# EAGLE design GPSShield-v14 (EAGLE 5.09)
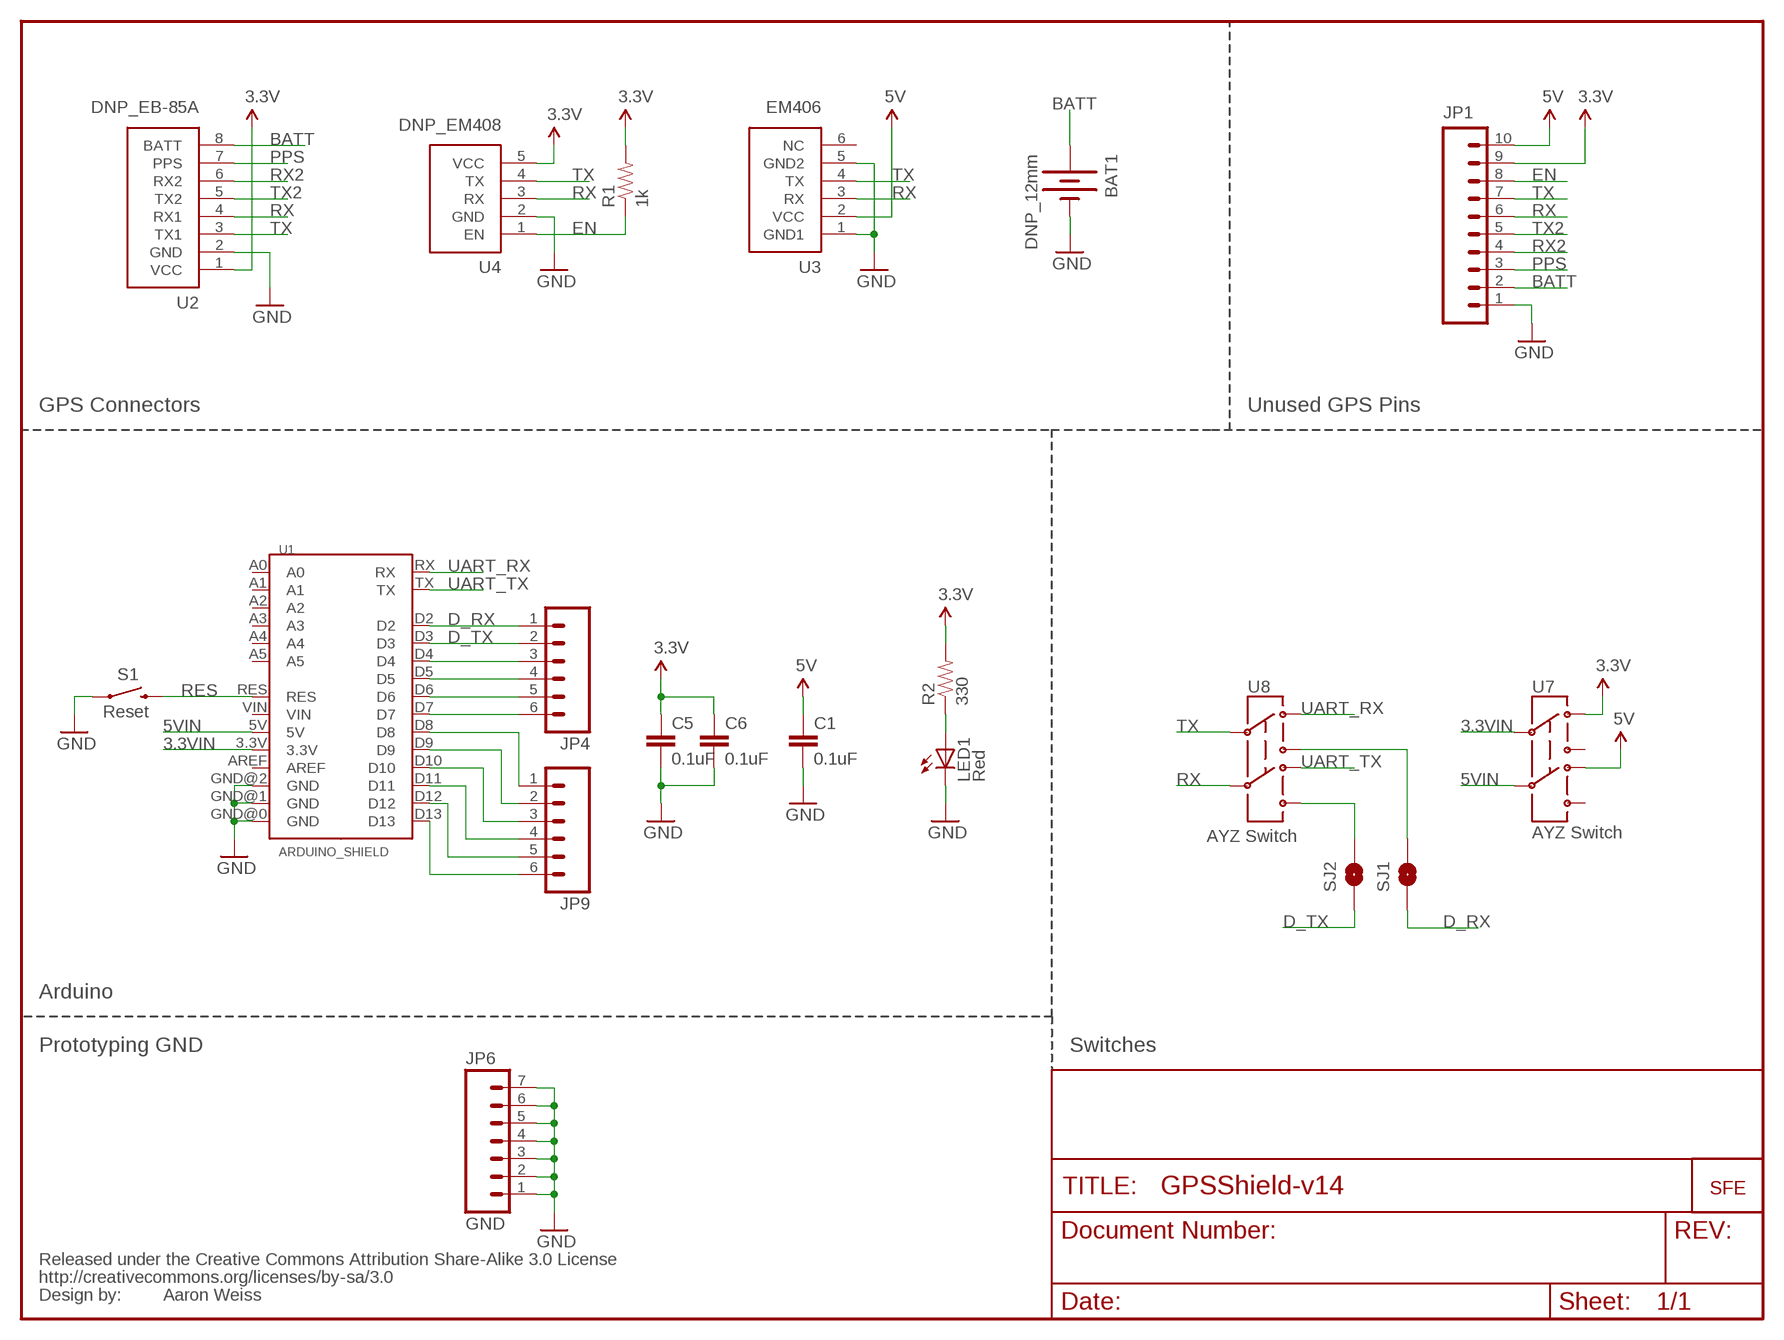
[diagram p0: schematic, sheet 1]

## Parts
BAT1  DNP_12mm  BATTERY12MM  [BATTCON_12MM]
C1  0.1uF  CAP0402-CAP  [0402-CAP]
C5  0.1uF  CAP0402-CAP  [0402-CAP]
C6  0.1uF  CAP0402-CAP  [0402-CAP]
JP1  M10"  [1X10]
JP3  LOGO-SFENEW  [SFE-NEW-WEBLOGO]
JP4  M06SIP  [1X06]
JP6  GND  M07  [1X07]
JP9  M06SIP  [1X06]
LED1  Red  LED0603  [LED-0603]
R1  1k  RESISTOR0402-RES  [0402-RES]
R2  330  RESISTOR0402-RES  [0402-RES]
S1  Reset  SWITCH-MOMENTARY-2SMD  [TACTILE_SWITCH_SMD]
SJ1  D_RX  SOLDERJUMPERNC  [SJ_2S]
SJ2  D_TX  SOLDERJUMPERNC  [SJ_2S]
U1  ARDUINO_SHIELD  [DUEMILANOVE_SHIELD]
U2  DNP_EB-85A  EB-85ASMD  [EB-85A]
U3  EM406  [EM406]
U4  DNP_EM408  EM408_CON  [EM408_CON]
U7  AYZ Switch  SWITCH-DPDTSMD  [AYZ0202]
U8  AYZ Switch  SWITCH-DPDTSMD  [AYZ0202]
U$1  CREATIVE_COMMONS  [CREATIVE_COMMONS]

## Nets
3.3V: C5.1 C6.1 JP1.9 R1.2 R2.2 U2.1(VCC) U4.5(VCC) U7.1
3.3VIN: U1.3.3V U7.2
5V: C1.1 JP1.10 U3.2(VCC) U7.4
5VIN: U1.5V U7.5
BATT: BAT1.PWR@1(+) JP1.2 U2.8(BATT)
D_RX: JP4.1 SJ1.1 U1.D2
D_TX: JP4.2 SJ2.1 U1.D3
EN: JP1.8 R1.1 U4.1(EN)
GND: BAT1.GND(-) C1.2 C5.2 C6.2 JP1.1 JP6.1 JP6.2 JP6.3 JP6.4 JP6.5 JP6.6 JP6.7 LED1.C S1.1 U1.GND@0(GND) U1.GND@1(GND) U1.GND@2(GND) U2.2(GND) U3.1(GND1) U3.5(GND2) U4.2(GND)
N$1: LED1.A R2.1
N$111: JP4.3 U1.D4
N$112: JP4.4 U1.D5
N$113: JP4.5 U1.D6
N$114: JP4.6 U1.D7
N$115: JP9.1 U1.D8
N$116: JP9.2 U1.D9
N$117: JP9.3 U1.D10
N$118: JP9.4 U1.D11
N$119: JP9.5 U1.D12
N$120: JP9.6 U1.D13
N$121: SJ2.2 U8.6
N$122: SJ1.2 U8.3
PPS: JP1.3 U2.7(PPS)
RES: S1.3 U1.RES
RX: JP1.6 U2.4(RX1) U3.3(RX) U4.3(RX) U8.5
RX2: JP1.4 U2.6(RX2)
TX: JP1.7 U2.3(TX1) U3.4(TX) U4.4(TX) U8.2
TX2: JP1.5 U2.5(TX2)
UART_RX: U1.RX U8.1
UART_TX: U1.TX U8.4
Unconnected: U1.A0 U1.A1 U1.A2 U1.A3 U1.A4 U1.A5 U1.AREF U1.VIN U3.6(NC) U7.3 U7.6

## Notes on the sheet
- GPS Connectors | Unused GPS Pins
- Arduino
- Prototyping GND | Switches
- Aaron Weiss

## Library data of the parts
BAT1 = SparkFun:BATTERY: Battery Holders
C1 C5 C6 = SparkFun:CAP: Capacitor
JP1 = SparkFun:M10: Header 10 Standard 10-pin 0.1" header. Use with straight break away headers (SKU : PRT-00116), right angle break away headers (PRT-00553), swiss pins (PRT-00743), machine pins (PRT-00117), and female headers (PRT-00115).
JP3 = SparkFun:LOGO-SFE: Spark Fun Electronics PCB Logo
JP4 JP9 = SparkFun:M06: Header 6 Standard 6-pin 0.1" header. Use with straight break away headers (SKU : PRT-00116), right angle break away headers (PRT-00553), swiss pins (PRT-00743), machine pins (PRT-00117), and female headers (PRT-00115). Molex polarized connector foot print use with SKU : PRT-08094 with associated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
JP6 = SparkFun:M07: Header 7 Standard 7-pin 0.1" header. Use with straight break away headers (SKU : PRT-00116), right angle break away headers (PRT-00553), swiss pins (PRT-00743), machine pins (PRT-00117), and female headers (PRT-00115). NOTES ON THE VARIANTS LOCK and LOCK_LONGPADS... This footprint was designed to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
LED1 = SparkFun:LED: LEDs
R1 R2 = SparkFun:RESISTOR: Resistor
S1 = SparkFun:SWITCH-MOMENTARY-2
SJ1 SJ2 = SparkFun:SOLDERJUMPER: Solder Jumper
U1 = SparkFun:ARDUINO_SHIELD
U2 = SparkFun:EB-85A: EB-85A Connector Proven layout and schematic for ETek 5Hz GPS receiver connector. Spark Fun Electronics SKU : GPS-08297
U3 = SparkFun:EM406: EM406 Connector Proven layout and schematic for EM406 connector. Spark Fun Electronics SKU : GPS-00579
U4 = SparkFun:EM408_CON: This is the mating connector for the EM408 GPS receiver. The EM408 connects to the board via a cable, this connector footprint does not include the outline of the receiver. You should include the "EM408_Outline" device in your schematic if you are to use the EM408 in your design.
U7 U8 = SparkFun:SWITCH-DPDT: DPDT Version of the COM-00597, MSS22 is a 125VAC @ 300mA rated switch
U$1 = SparkFun:CREATIVE_COMMONS

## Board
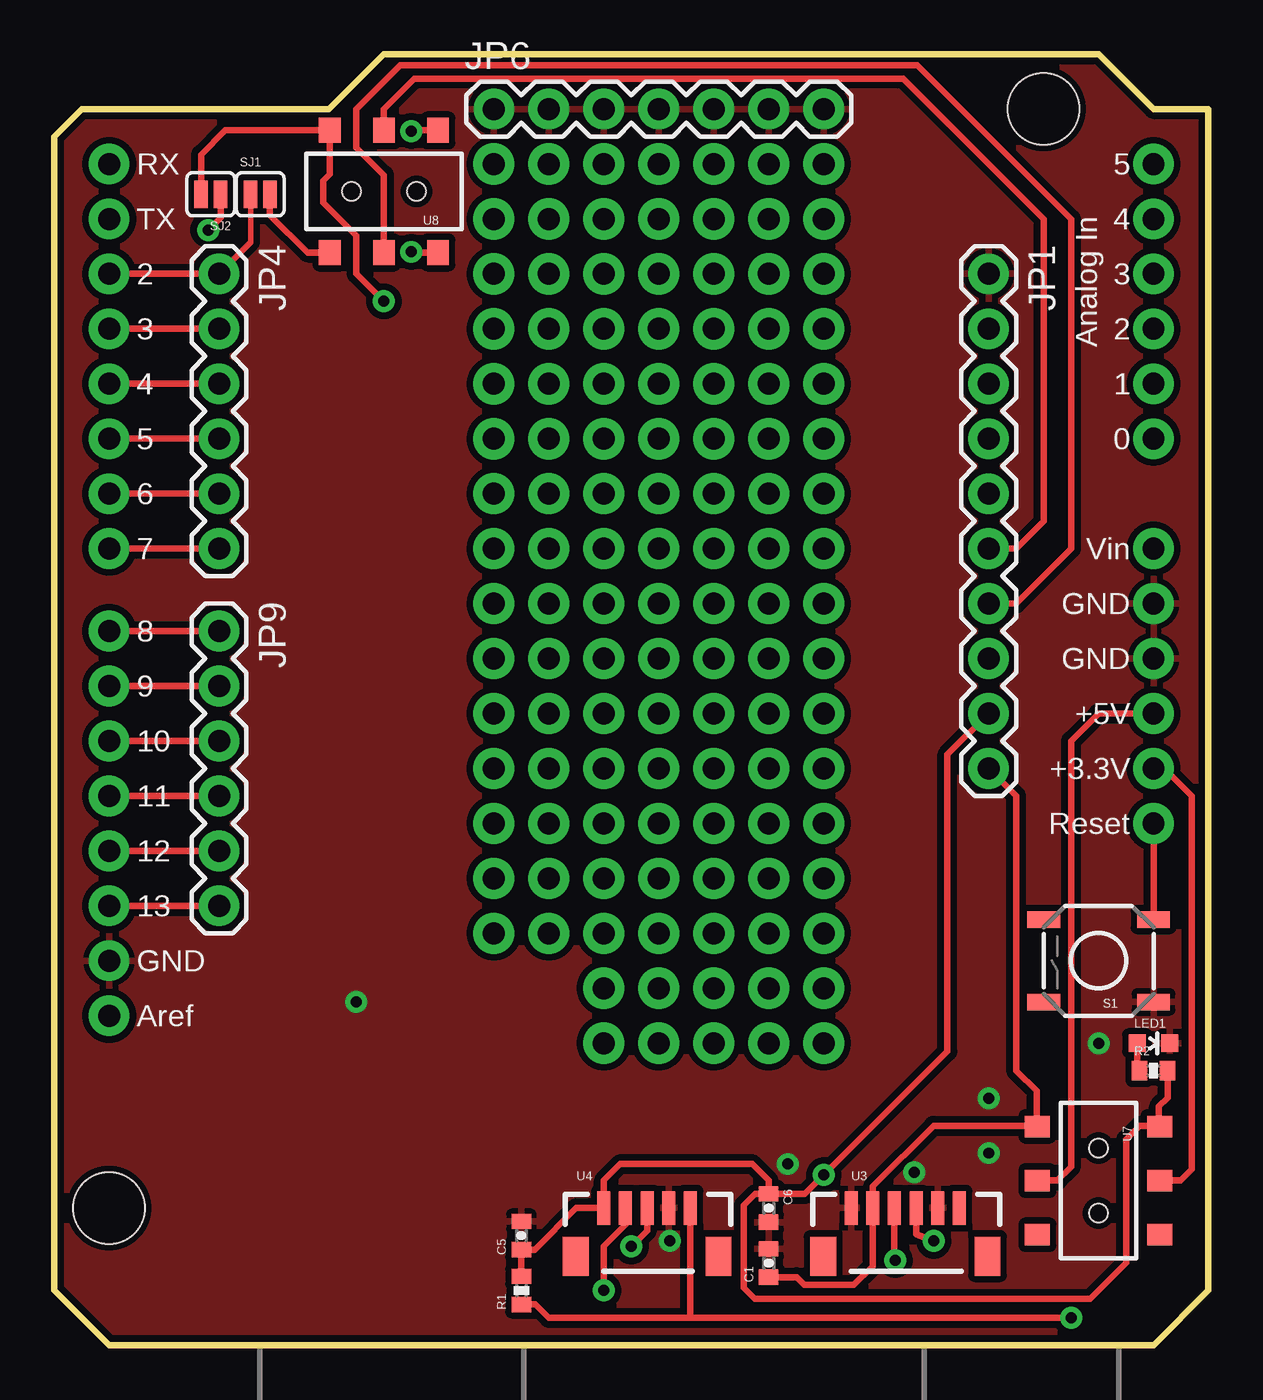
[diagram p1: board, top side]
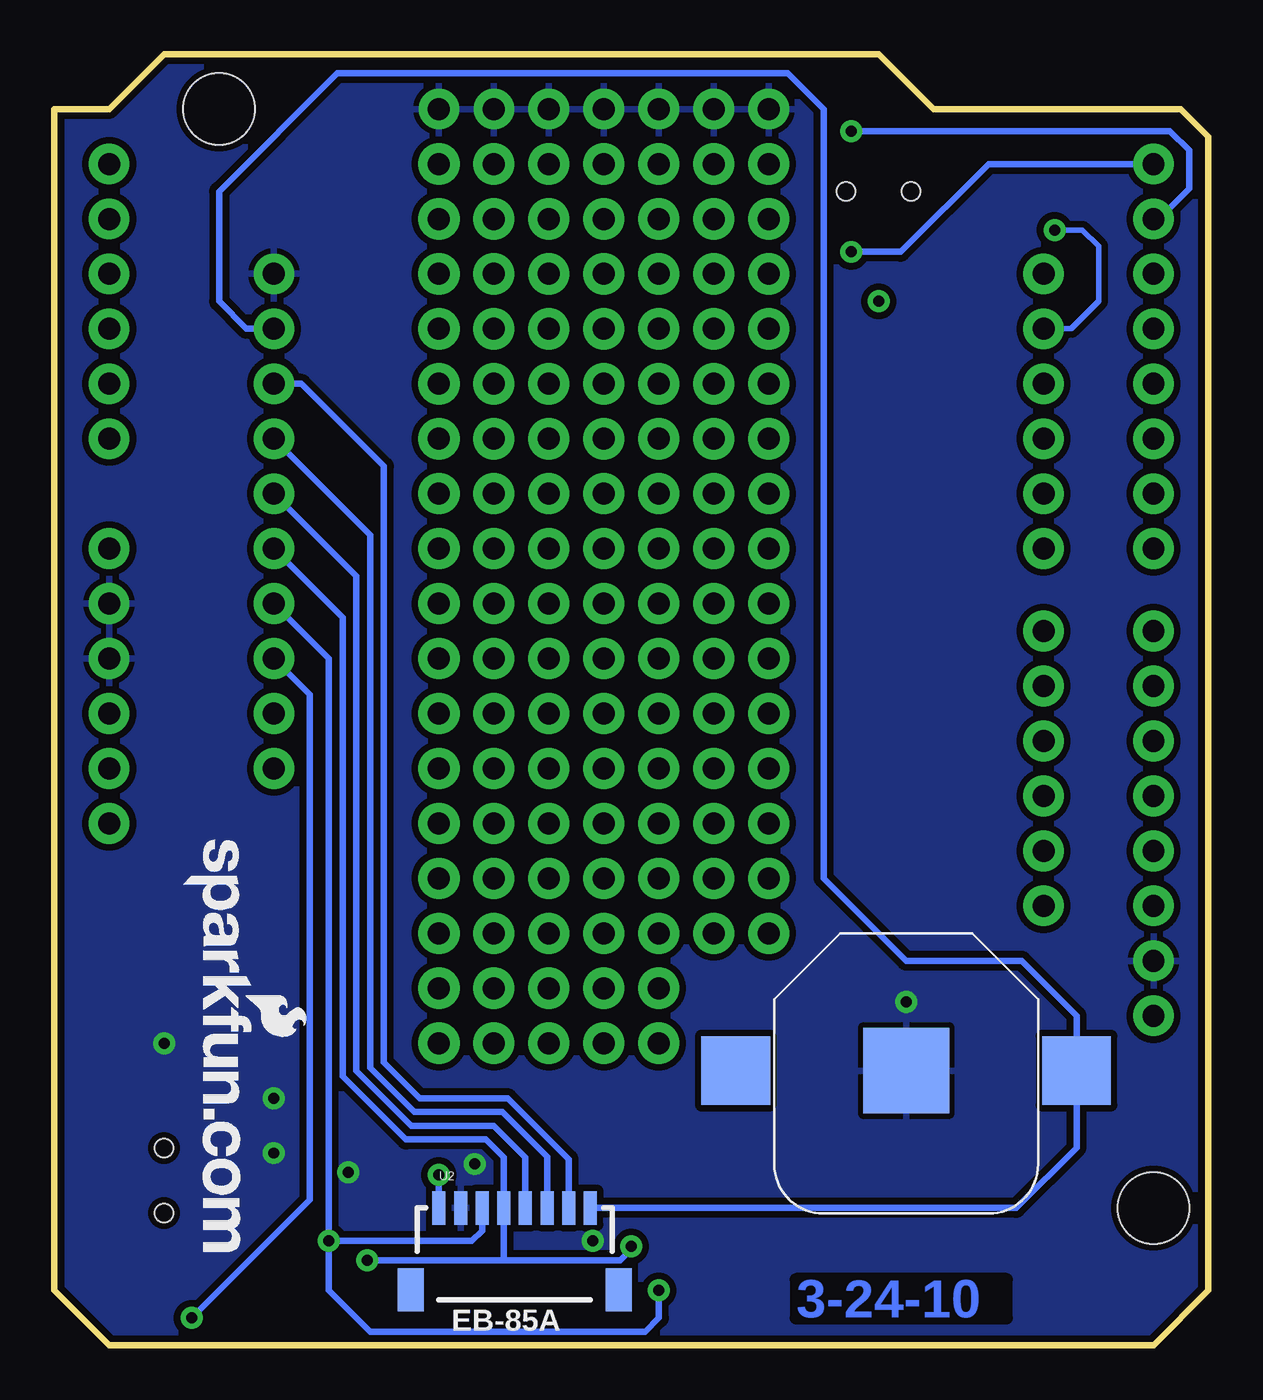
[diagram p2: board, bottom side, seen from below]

Size 53.34 x 59.69 mm. Coordinates in mm from the lower left corner, seen from the top.
Outline: 2.54,0 0,2.54 0,55.88 1.27,57.15 12.7,57.15 15.24,59.69 48.26,59.69 50.8,57.15 53.34,57.15 53.34,2.54 50.8,0 2.54,0
Copper layers (1*16): Top 0.035mm / dielectric 1.5mm / Bottom 0.035mm
Design rules "SparkFun": minimum track width 8mil, minimum drill 20mil, track to track 8mil, track to pad 8mil, pad to pad 8mil, via to via 8mil, smd to smd 8mil, copper to edge 8mil, drill to drill 8mil, minimum pad ring 12mil, minimum via ring 10mil, stop-mask expansion 4mil, vias tented up to drill 20mil, thermal gap 10mil

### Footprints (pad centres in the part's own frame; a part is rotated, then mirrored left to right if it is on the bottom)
BATTCON_12MM = smd 3.962 x 3.962: GND 0,0 | smd 3.175 x 3.175: PWR@1 -7.874,0; PWR@2 7.874,0
0402-CAP = smd 0.7 x 0.9: 1 -0.65,0; 2 0.65,0
1X10 = drill 1.016 pad 1.88 round: 1 0,0; 2 2.54,0; 3 5.08,0; 4 7.62,0; 5 10.16,0; 6 12.7,0; 7 15.24,0; 8 17.78,0; 9 20.32,0; 10 22.86,0
1X06 = drill 1.016 pad 1.88 round: 1 0,0; 2 2.54,0; 3 5.08,0; 4 7.62,0; 5 10.16,0; 6 12.7,0
1X07 = drill 1.016 pad 1.88 round: 1 0,0; 2 2.54,0; 3 5.08,0; 4 7.62,0; 5 10.16,0; 6 12.7,0; 7 15.24,0
LED-0603 = smd 0.8 x 0.8: A 0,-0.75; C 0,0.75
0402-RES = smd 0.7 x 0.9: 1 -0.65,0; 2 0.65,0
TACTILE_SWITCH_SMD = smd 1.524 x 0.762: 1 -2.54,1.905; 2 2.54,1.905; 3 -2.54,-1.905; 4 2.54,-1.905
SJ_2S = smd 0.635 x 1.27: 1 -0.45,0; 2 0.45,0
DUEMILANOVE_SHIELD = drill 1.016 pad 1.88 round: 3.3V 50.8,26.67; 5V 50.8,29.21; A0 50.8,41.91; A1 50.8,44.45; A2 50.8,46.99; A3 50.8,49.53; A4 50.8,52.07; A5 50.8,54.61; AREF 2.54,15.24; D2 2.54,49.53; D3 2.54,46.99; D4 2.54,44.45; D5 2.54,41.91; D6 2.54,39.37; D7 2.54,36.83; D8 2.54,33.02; D9 2.54,30.48; D10 2.54,27.94; D11 2.54,25.4; D12 2.54,22.86; D13 2.54,20.32; GND@0 50.8,31.75; GND@1 50.8,34.29; GND@2 2.54,17.78; RES 50.8,24.13; RX 2.54,54.61; TX 2.54,52.07; VIN 50.8,36.83 | hole 3.302: 45.72,57.15; 2.54,6.35
EB-85A = smd 0.6 x 1.55: 1 0,0; 2 1,0; 3 2,0; 4 3,0; 5 4,0; 6 5,0; 7 6,0; 8 7,0 | smd 1.2 x 2: P$1 -1.3,-3.775; P$2 8.3,-3.775
EM406 = smd 0.6 x 1.55: 1 0,0; 2 1,0; 3 2,0; 4 3,0; 5 4,0; 6 5,0 | smd 1.2 x 1.8: P$1 -1.3,-2.225; P$2 6.3,-2.225
EM408_CON = smd 0.6 x 1.55: 1 4,0; 2 3,0; 3 2,0; 4 1,0; 5 0,0 | smd 1.2 x 1.8: P$1 -1.3,-2.225; P$2 5.3,-2.225
AYZ0202 = smd 1 x 1.15: 1 -2.5,2.825; 2 0,2.825; 3 2.5,2.825; 4 -2.5,-2.825; 5 0,-2.825; 6 2.5,-2.825 | hole 0.85: 1.5,0; -1.5,0

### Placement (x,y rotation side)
BAT1  13.97,12.7 180 bottom
C1  33.02,3.81 90 top
C5  21.59,5.08 90 top
C6  33.02,6.35 270 top
JP1  43.18,49.53 270 top
JP3  47.37,23.37 270 bottom
JP4  7.62,49.53 270 top
JP6  20.32,57.15 0 top
JP9  7.62,33.02 270 top
LED1  50.8,13.97 270 top
R1  21.59,2.54 90 top
R2  50.8,12.7 0 top
S1  48.26,17.78 180 top
SJ1  9.53,53.21 0 top
SJ2  7.24,53.21 180 top
U1  0,0 0 top
U2  35.56,6.35 0 bottom
U3  36.83,6.35 0 top
U4  25.4,6.35 0 top
U7  48.26,7.62 270 top
U8  15.24,53.34 180 top
U$1  not placed on the board

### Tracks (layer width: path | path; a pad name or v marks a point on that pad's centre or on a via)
3.3V  (via drill 0.51)
  Top 0.305: 51.05,10.16 50.16,10.16 49.53,9.53 49.53,3.81 47.88,2.16 32.38,2.16 31.88,2.67 31.88,6.48 32.4,7 C6.1 | 51.05,10.16 U7.1 | JP1.9 41.27,27.3 41.27,13.59 v35.56,7.87 34.69,7 C6.1 | C6.1 33.02,7.62 32.26,8.38 26.16,8.38 25.4,7.62 U4.5 24.13,6.35 22.21,4.43 C5.1 R1.2 | 51.05,10.16 51.05,11.04 51.45,11.45 R2.2
  Bottom 0.305: v35.56,7.87 U2.1
3.3VIN
  Top 0.305: U1.3.3V 51.31,26.67 52.58,25.4 52.58,8.13 52.07,7.62 U7.2
5V
  Top 0.305: C1.1 34.3,3.16 34.67,2.79 36.96,2.79 37.83,3.67 U3.2 37.83,7.35 40.64,10.16 45.4,10.16 | 45.4,10.16 U7.4 | 45.4,10.16 45.4,11.76 44.45,12.7 44.45,25.4 JP1.10
5VIN
  Top 0.305: U1.5V 48.26,29.21 46.99,27.94 46.99,8.26 46.35,7.62 U7.5
BATT
  Bottom 0.305: JP1.2 44.45,46.99 45.72,48.26 45.72,53.34 40.26,58.8 19.43,58.8 17.78,57.15 17.78,21.59 13.97,17.78 8.64,17.78 6.1,15.24 BAT1.PWR@1 6.1,9.14 8.89,6.35 U2.8
D_RX
  Top 0.254: SJ1.1 9.07,50.98 JP4.1
  Top 0.305: U1.D2 JP4.1
D_TX  (via drill 0.51)
  Top 0.305: U1.D3 JP4.2 | SJ2.1 7.69,52.14 v7.11,51.56
  Bottom 0.254: JP4.2 6.35,46.99 5.08,48.26 5.08,50.8 5.84,51.56 v7.11,51.56
EN  (via drill 0.51)
  Top 0.305: 29.46,1.27 v46.99,1.27 | U4.1 29.4,1.33 29.46,1.27 | 29.46,1.27 22.86,1.27 22.24,1.89 R1.1
  Bottom 0.305: JP1.8 41.53,30.1 41.53,6.73 v46.99,1.27
GND  (via drill 0.51)
  other vias: 28.45,4.83 48.26,13.97 43.18,11.43 33.91,8.38 43.18,8.89 13.97,15.88 39.75,8
  pour Top (isolate 0.305): 0,0 0,59.69 53.34,59.69 53.34,0
  pour Bottom (isolate 0.305): 0,0 0,59.69 53.34,59.69 53.34,0
N$1
  Top 0.305: LED1.A 50.05,12.8 R2.1
N$2  (via drill 1.02 pad 1.91)
  other vias: 22.86,54.61
N$3  (via drill 1.02 pad 1.91)
  other vias: 22.86,29.21
N$4  (via drill 1.02 pad 1.91)
  other vias: 22.86,36.83
N$5  (via drill 1.02 pad 1.91)
  other vias: 22.86,39.37
N$6  (via drill 1.02 pad 1.91)
  other vias: 22.86,41.91
N$7  (via drill 1.02 pad 1.91)
  other vias: 22.86,44.45
N$8  (via drill 1.02 pad 1.91)
  other vias: 22.86,46.99
N$9  (via drill 1.02 pad 1.91)
  other vias: 22.86,49.53
N$10  (via drill 1.02 pad 1.91)
  other vias: 22.86,52.07
N$11  (via drill 1.02 pad 1.91)
  other vias: 22.86,34.29
N$12  (via drill 1.02 pad 1.91)
  other vias: 22.86,31.75
N$13  (via drill 1.02 pad 1.91)
  other vias: 22.86,26.67
N$14  (via drill 1.02 pad 1.91)
  other vias: 20.32,36.83
N$15  (via drill 1.02 pad 1.91)
  other vias: 20.32,39.37
N$16  (via drill 1.02 pad 1.91)
  other vias: 20.32,41.91
N$17  (via drill 1.02 pad 1.91)
  other vias: 20.32,44.45
N$18  (via drill 1.02 pad 1.91)
  other vias: 20.32,46.99
N$19  (via drill 1.02 pad 1.91)
  other vias: 20.32,49.53
N$20  (via drill 1.02 pad 1.91)
  other vias: 20.32,54.61
N$21  (via drill 1.02 pad 1.91)
  other vias: 20.32,52.07
N$22  (via drill 1.02 pad 1.91)
  other vias: 20.32,34.29
N$23  (via drill 1.02 pad 1.91)
  other vias: 20.32,31.75
N$24  (via drill 1.02 pad 1.91)
  other vias: 20.32,29.21
N$25  (via drill 1.02 pad 1.91)
  other vias: 20.32,26.67
N$26  (via drill 1.02 pad 1.91)
  other vias: 25.4,36.83
N$27  (via drill 1.02 pad 1.91)
  other vias: 25.4,39.37
N$28  (via drill 1.02 pad 1.91)
  other vias: 25.4,41.91
N$29  (via drill 1.02 pad 1.91)
  other vias: 25.4,44.45
N$30  (via drill 1.02 pad 1.91)
  other vias: 25.4,46.99
N$31  (via drill 1.02 pad 1.91)
  other vias: 25.4,49.53
N$32  (via drill 1.02 pad 1.91)
  other vias: 25.4,54.61
N$33  (via drill 1.02 pad 1.91)
  other vias: 25.4,52.07
N$34  (via drill 1.02 pad 1.91)
  other vias: 25.4,34.29
N$35  (via drill 1.02 pad 1.91)
  other vias: 25.4,31.75
N$36  (via drill 1.02 pad 1.91)
  other vias: 25.4,29.21
N$37  (via drill 1.02 pad 1.91)
  other vias: 25.4,26.67
N$38  (via drill 1.02 pad 1.91)
  other vias: 27.94,36.83
N$39  (via drill 1.02 pad 1.91)
  other vias: 27.94,39.37
N$40  (via drill 1.02 pad 1.91)
  other vias: 27.94,41.91
N$41  (via drill 1.02 pad 1.91)
  other vias: 27.94,44.45
N$42  (via drill 1.02 pad 1.91)
  other vias: 27.94,46.99
N$43  (via drill 1.02 pad 1.91)
  other vias: 27.94,49.53
N$44  (via drill 1.02 pad 1.91)
  other vias: 27.94,54.61
N$45  (via drill 1.02 pad 1.91)
  other vias: 27.94,52.07
N$46  (via drill 1.02 pad 1.91)
  other vias: 27.94,34.29
N$47  (via drill 1.02 pad 1.91)
  other vias: 27.94,31.75
N$48  (via drill 1.02 pad 1.91)
  other vias: 27.94,29.21
N$49  (via drill 1.02 pad 1.91)
  other vias: 27.94,26.67
N$50  (via drill 1.02 pad 1.91)
  other vias: 30.48,36.83
N$51  (via drill 1.02 pad 1.91)
  other vias: 30.48,39.37
N$52  (via drill 1.02 pad 1.91)
  other vias: 30.48,41.91
N$53  (via drill 1.02 pad 1.91)
  other vias: 30.48,44.45
N$54  (via drill 1.02 pad 1.91)
  other vias: 30.48,46.99
N$55  (via drill 1.02 pad 1.91)
  other vias: 30.48,49.53
N$56  (via drill 1.02 pad 1.91)
  other vias: 30.48,54.61
N$57  (via drill 1.02 pad 1.91)
  other vias: 30.48,52.07
N$58  (via drill 1.02 pad 1.91)
  other vias: 30.48,34.29
N$59  (via drill 1.02 pad 1.91)
  other vias: 30.48,31.75
N$60  (via drill 1.02 pad 1.91)
  other vias: 30.48,29.21
N$61  (via drill 1.02 pad 1.91)
  other vias: 30.48,26.67
N$62  (via drill 1.02 pad 1.91)
  other vias: 33.02,36.83
N$63  (via drill 1.02 pad 1.91)
  other vias: 33.02,39.37
N$64  (via drill 1.02 pad 1.91)
  other vias: 33.02,41.91
N$65  (via drill 1.02 pad 1.91)
  other vias: 33.02,44.45
N$66  (via drill 1.02 pad 1.91)
  other vias: 33.02,46.99
N$67  (via drill 1.02 pad 1.91)
  other vias: 33.02,49.53
N$68  (via drill 1.02 pad 1.91)
  other vias: 33.02,54.61
N$69  (via drill 1.02 pad 1.91)
  other vias: 33.02,52.07
N$70  (via drill 1.02 pad 1.91)
  other vias: 33.02,34.29
N$71  (via drill 1.02 pad 1.91)
  other vias: 33.02,31.75
N$72  (via drill 1.02 pad 1.91)
  other vias: 33.02,29.21
N$73  (via drill 1.02 pad 1.91)
  other vias: 33.02,26.67
N$74  (via drill 1.02 pad 1.91)
  other vias: 35.56,36.83
N$75  (via drill 1.02 pad 1.91)
  other vias: 35.56,39.37
N$76  (via drill 1.02 pad 1.91)
  other vias: 35.56,41.91
N$77  (via drill 1.02 pad 1.91)
  other vias: 35.56,44.45
N$78  (via drill 1.02 pad 1.91)
  other vias: 35.56,46.99
N$79  (via drill 1.02 pad 1.91)
  other vias: 35.56,49.53
N$80  (via drill 1.02 pad 1.91)
  other vias: 35.56,54.61
N$81  (via drill 1.02 pad 1.91)
  other vias: 35.56,52.07
N$82  (via drill 1.02 pad 1.91)
  other vias: 35.56,34.29
N$83  (via drill 1.02 pad 1.91)
  other vias: 35.56,31.75
N$84  (via drill 1.02 pad 1.91)
  other vias: 35.56,29.21
N$85  (via drill 1.02 pad 1.91)
  other vias: 35.56,26.67
N$86  (via drill 1.02 pad 1.91)
  other vias: 35.56,24.13
N$87  (via drill 1.02 pad 1.91)
  other vias: 35.56,21.59
N$88  (via drill 1.02 pad 1.91)
  other vias: 35.56,19.05
N$89  (via drill 1.02 pad 1.91)
  other vias: 35.56,16.51
N$90  (via drill 1.02 pad 1.91)
  other vias: 35.56,13.97
N$91  (via drill 1.02 pad 1.91)
  other vias: 33.02,24.13
N$92  (via drill 1.02 pad 1.91)
  other vias: 33.02,21.59
N$93  (via drill 1.02 pad 1.91)
  other vias: 33.02,19.05
N$94  (via drill 1.02 pad 1.91)
  other vias: 33.02,16.51
N$95  (via drill 1.02 pad 1.91)
  other vias: 33.02,13.97
N$96  (via drill 1.02 pad 1.91)
  other vias: 30.48,24.13
N$97  (via drill 1.02 pad 1.91)
  other vias: 30.48,21.59
N$98  (via drill 1.02 pad 1.91)
  other vias: 30.48,19.05
N$99  (via drill 1.02 pad 1.91)
  other vias: 30.48,16.51
N$100  (via drill 1.02 pad 1.91)
  other vias: 30.48,13.97
N$101  (via drill 1.02 pad 1.91)
  other vias: 27.94,24.13
N$102  (via drill 1.02 pad 1.91)
  other vias: 27.94,21.59
N$103  (via drill 1.02 pad 1.91)
  other vias: 27.94,19.05
N$104  (via drill 1.02 pad 1.91)
  other vias: 27.94,16.51
N$105  (via drill 1.02 pad 1.91)
  other vias: 27.94,13.97
N$106  (via drill 1.02 pad 1.91)
  other vias: 25.4,24.13
N$107  (via drill 1.02 pad 1.91)
  other vias: 25.4,21.59
N$108  (via drill 1.02 pad 1.91)
  other vias: 25.4,19.05
N$109  (via drill 1.02 pad 1.91)
  other vias: 25.4,16.51
N$110  (via drill 1.02 pad 1.91)
  other vias: 25.4,13.97
N$111
  Top 0.305: U1.D4 JP4.3
N$112
  Top 0.305: U1.D5 JP4.4
N$113
  Top 0.305: U1.D6 JP4.5
N$114
  Top 0.305: U1.D7 JP4.6
N$115
  Top 0.305: U1.D8 JP9.1
N$116
  Top 0.305: U1.D9 JP9.2
N$117
  Top 0.305: U1.D10 JP9.3
N$118
  Top 0.305: U1.D11 JP9.4
N$119
  Top 0.305: U1.D12 JP9.5
N$120
  Top 0.305: U1.D13 JP9.6
N$121  (via drill 0.51)
  Top 0.305: v15.24,48.26 13.97,49.53 13.97,51.31 12.45,52.83 12.45,53.85 12.74,54.14 U8.6 7.91,56.16 6.79,55.05 SJ2.2
N$122
  Top 0.305: SJ1.2 9.97,52.26 11.71,50.52 U8.3
N$123  (via drill 1.02 pad 1.91)
  other vias: 22.86,19.05
N$124  (via drill 1.02 pad 1.91)
  other vias: 20.32,21.59
N$125  (via drill 1.02 pad 1.91)
  other vias: 20.32,24.13
N$126  (via drill 1.02 pad 1.91)
  other vias: 22.86,24.13
N$127  (via drill 1.02 pad 1.91)
  other vias: 22.86,21.59
N$128  (via drill 1.02 pad 1.91)
  other vias: 20.32,19.05
PPS
  Bottom 0.305: U2.7 29.56,8.61 32.38,11.43 36.45,11.43 38.1,13.08 38.1,40.64 41.91,44.45 JP1.3
RES
  Top 0.305: S1.3 U1.RES
RX  (via drill 0.51)
  Top 0.305: U3.3 38.83,3.97 v38.86,3.94 | U4.3 27.4,5.3 v26.67,4.57 | JP1.6 44.45,36.83 45.72,38.1 45.72,52.07 39.24,58.55 16.64,58.55 15.24,57.15 U8.5
  Bottom 0.305: 32.51,3.94 v38.86,3.94 | 32.51,3.94 32.56,3.98 U2.4 32.56,8.68 33.4,9.53 37.08,9.53 40.01,12.45 40.01,33.66 JP1.6 | v26.67,4.57 26.67,4.45 27.18,3.94 32.51,3.94
RX2
  Bottom 0.305: U2.6 30.56,8.72 32.64,10.79 36.7,10.79 38.73,12.83 38.73,37.47 JP1.4
TX  (via drill 0.51)
  Top 0.305: U3.4 39.83,5.13 v40.64,4.83 | U4.4 26.4,5.57 25.4,4.57 v25.4,2.54 | JP1.7 44.45,34.29 46.99,36.83 46.99,52.07 39.88,59.18 16,59.18 13.97,57.15 13.97,55.37 15.24,54.1 U8.2
  Bottom 0.305: U2.3 33.56,5.3 34.04,4.83 v40.64,4.83 | v40.64,4.83 40.64,5.08 | v25.4,2.54 25.4,1.27 26.04,0.64 38.73,0.64 40.64,2.54 v40.64,4.83 | JP1.7 40.64,31.75 v40.64,4.83
TX2
  Bottom 0.305: U2.5 31.56,8.7 33.02,10.16 36.83,10.16 39.37,12.7 39.37,35.56 JP1.5
UART_RX  (via drill 0.51)
  Top 0.305: U8.1 16.54,50.52 v16.51,50.55
  Bottom 0.305: v16.51,50.55 14.22,50.55 10.16,54.61 U1.RX
UART_TX  (via drill 0.51)
  Top 0.305: U8.4 16.54,56.16 v16.51,56.13
  Bottom 0.305: U1.TX 2.29,52.07 0.89,53.47 0.89,55.24 1.78,56.13 v16.51,56.13

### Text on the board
Bottom: 3-24-10
bPlace: EB-85A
